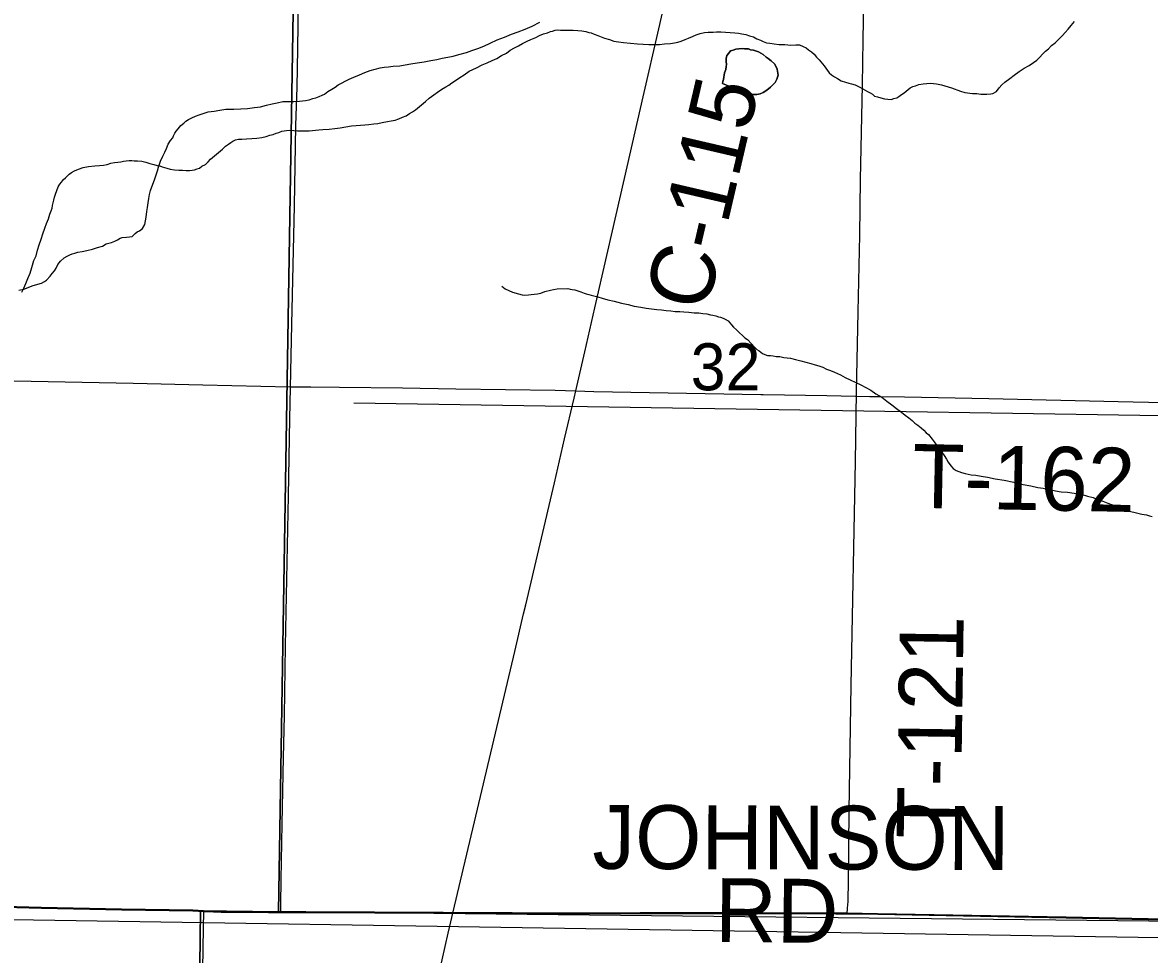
# Model space of a CAD drawing. Extents: x 2.4 to 73.1, y 4.5 to 25.6.
# Drawn here: x 43.39 to 43.892, y 18.583 to 18.998 of the extents above; entities that cross this region are included whole.
import ezdxf

# ---------------------------------------------------------------- set-up
doc = ezdxf.new("R2010")
doc.units = 0
for name, color, linetype in [('GM_X_County_Road', 7, 'Continuous'), ('GM_X_County_Road_Text', 7, 'Continuous'), ('GM_X_Interchange_Ramps', 7, 'Continuous'), ('GM_X_Minor_Lake', 7, 'Continuous'), ('GM_X_Minor_River', 7, 'Continuous'), ('GM_X_Section', 7, 'Continuous'), ('GM_X_Section_Text', 7, 'Continuous'), ('GM_X_Township', 7, 'Continuous'), ('GM_X_Township_Road', 7, 'Continuous'), ('GM_X_Township_Road_Text', 7, 'Continuous'), ('GM_X_US_Shield', 7, 'Continuous')]:
    doc.layers.add(name, color=color, linetype=linetype)

msp = doc.modelspace()

# ---------------------------------------------------------------- linework, layer by layer
at = {"layer": 'GM_X_County_Road'}
msp.add_line((43.60907, 18.71768), (43.61292, 18.73432), dxfattribs=at)
for points in [[(43.63623, 18.83366), (43.6402, 18.85095), (43.64472, 18.87063), (43.65791, 18.92819), (43.66613, 18.96457), (43.67319, 18.99479), (43.67664, 19.00993), (43.68375, 19.04178), (43.69135, 19.07512), (43.6983, 19.10383), (43.70422, 19.12638), (43.71071, 19.15039), (43.7175, 19.1743), (43.72344, 19.19524), (43.74391, 19.26696), (43.75788, 19.3163), (43.76276, 19.33357)], [(43.61292, 18.73432), (43.61388, 18.73842), (43.62668, 18.79269), (43.63123, 18.81232), (43.63547, 18.83041), (43.63623, 18.83366)], [(43.57593, 18.57695), (43.57673, 18.58043), (43.57937, 18.59218), (43.58222, 18.60427), (43.59509, 18.65871), (43.60907, 18.71768)]]:
    msp.add_lwpolyline(points, dxfattribs=at)
at = {"layer": 'GM_X_Interchange_Ramps'}
msp.add_lwpolyline([(43.9276, 18.59787), (43.85453, 18.5994), (43.77058, 18.6009), (43.757, 18.60107), (43.75192, 18.60113), (43.70838, 18.60123), (43.66485, 18.60125), (43.63841, 18.60118), (43.51594, 18.60166), (43.50475, 18.60171), (43.49917, 18.60173), (43.48509, 18.60186), (43.47809, 18.60192), (43.47479, 18.60206), (43.47037, 18.60218), (43.4656, 18.6024), (43.4339, 18.60285), (43.39809, 18.6036), (43.34828, 18.60502)], dxfattribs=at)
at = {"layer": 'GM_X_Minor_Lake'}
for points in [[(43.7197, 18.98329), (43.71857, 18.98389), (43.71763, 18.98448), (43.71669, 18.98488), (43.71537, 18.98529), (43.71405, 18.98551), (43.7131, 18.98591), (43.71139, 18.98595), (43.71025, 18.98597), (43.70873, 18.98582), (43.7074, 18.98566), (43.70625, 18.9853), (43.7051, 18.98495), (43.70432, 18.98402), (43.70353, 18.9829), (43.70312, 18.98158), (43.70309, 18.98025), (43.70325, 18.97892), (43.70323, 18.97797), (43.70301, 18.97664), (43.7024, 18.97514), (43.70196, 18.9723), (43.70175, 18.97135), (43.70154, 18.97041)], [(43.70154, 18.97041), (43.70175, 18.97135), (43.70196, 18.9723), (43.7024, 18.97514), (43.70301, 18.97664), (43.70323, 18.97797), (43.70325, 18.97892), (43.70309, 18.98025), (43.70312, 18.98158), (43.70353, 18.9829), (43.70432, 18.98402), (43.7051, 18.98495), (43.70625, 18.9853), (43.7074, 18.98566), (43.70873, 18.98582), (43.71025, 18.98597), (43.71139, 18.98595), (43.7131, 18.98591), (43.71405, 18.98551), (43.71537, 18.98529), (43.71669, 18.98488), (43.71763, 18.98448), (43.71857, 18.98389), (43.7197, 18.98329), (43.721, 18.98212), (43.72194, 18.98153), (43.72325, 18.98055), (43.72474, 18.97919), (43.72547, 18.97784), (43.72583, 18.97688), (43.72634, 18.97421), (43.72572, 18.97233), (43.72493, 18.97083), (43.72376, 18.96971), (43.72298, 18.96878), (43.72202, 18.96804), (43.72085, 18.96712), (43.7197, 18.96639), (43.71835, 18.96585), (43.71682, 18.9655), (43.71549, 18.96553), (43.71359, 18.96558), (43.71189, 18.9658), (43.71019, 18.96641), (43.70868, 18.96702), (43.70737, 18.96781), (43.70587, 18.9686), (43.70154, 18.97041)], [(43.70154, 18.97041), (43.70587, 18.9686), (43.70737, 18.96781), (43.70868, 18.96702), (43.71019, 18.96641), (43.71189, 18.9658), (43.71359, 18.96558), (43.71549, 18.96553), (43.71682, 18.9655), (43.71835, 18.96585), (43.7197, 18.96639), (43.72085, 18.96712), (43.72202, 18.96804), (43.72298, 18.96878), (43.72376, 18.96971), (43.72493, 18.97083), (43.72572, 18.97233), (43.72634, 18.97421), (43.72583, 18.97688), (43.72547, 18.97784), (43.72474, 18.97919), (43.72325, 18.98055), (43.72194, 18.98153), (43.721, 18.98212), (43.7197, 18.98329)]]:
    msp.add_lwpolyline(points, dxfattribs=at)
at = {"layer": 'GM_X_Minor_River'}
for points in [[(43.47253, 18.95781), (43.4752, 18.95813), (43.47768, 18.95864), (43.48035, 18.95896), (43.48396, 18.95907), (43.48701, 18.95919), (43.49005, 18.95931), (43.4931, 18.95981), (43.49577, 18.96013), (43.49845, 18.96083), (43.50093, 18.96134), (43.50323, 18.96186), (43.50571, 18.96237), (43.508, 18.96251), (43.51066, 18.96245), (43.51313, 18.96259), (43.5158, 18.96291), (43.51752, 18.96325), (43.51905, 18.96378), (43.52039, 18.96413), (43.52192, 18.96467), (43.52326, 18.96521), (43.52423, 18.96575), (43.52577, 18.96686), (43.52751, 18.96796), (43.52905, 18.96887), (43.5304, 18.96979), (43.53521, 18.97234), (43.53732, 18.97324), (43.53982, 18.97433), (43.54232, 18.97541), (43.54462, 18.97631), (43.54691, 18.97683), (43.54901, 18.97735), (43.55092, 18.97769), (43.55283, 18.97783), (43.55492, 18.97816), (43.55778, 18.97829), (43.56026, 18.9788), (43.56274, 18.97913), (43.5656, 18.97963), (43.56866, 18.98013), (43.57171, 18.98063), (43.57438, 18.98114), (43.57668, 18.98166), (43.57916, 18.98217), (43.58164, 18.98269), (43.58413, 18.98339), (43.58757, 18.98426), (43.58987, 18.98516), (43.59255, 18.98605), (43.59524, 18.98713), (43.59812, 18.98839), (43.60119, 18.98984), (43.60446, 18.9911), (43.60753, 18.99236), (43.61059, 18.99343), (43.61366, 18.99469), (43.61673, 18.99595), (43.62019, 18.99777)], [(43.76234, 18.96903), (43.76403, 18.96804), (43.76609, 18.96685), (43.76722, 18.96626), (43.76835, 18.96566), (43.76928, 18.96488), (43.7706, 18.96447), (43.77211, 18.96406), (43.77363, 18.96364), (43.77514, 18.96342), (43.77666, 18.96338), (43.77781, 18.96374), (43.77915, 18.96409), (43.78011, 18.96464), (43.78127, 18.96556), (43.78243, 18.96629), (43.78418, 18.96777), (43.78514, 18.96851), (43.7863, 18.96905), (43.78744, 18.96941), (43.78898, 18.96994), (43.79089, 18.97028), (43.79412, 18.97059), (43.79678, 18.97034), (43.79905, 18.9699), (43.80358, 18.96847), (43.80754, 18.96705), (43.80943, 18.96644), (43.81284, 18.96598), (43.81474, 18.96594), (43.81664, 18.96571), (43.8193, 18.96564), (43.82101, 18.9658), (43.82197, 18.96596), (43.82351, 18.96688), (43.82469, 18.96856), (43.82586, 18.96986), (43.82721, 18.97097), (43.82953, 18.97263), (43.83147, 18.97411), (43.83359, 18.97577), (43.83591, 18.97723), (43.83803, 18.97851), (43.83996, 18.9798), (43.8415, 18.98091), (43.84287, 18.9822), (43.84403, 18.98351), (43.8454, 18.98481), (43.84675, 18.98591), (43.84812, 18.9874), (43.84966, 18.98851), (43.85083, 18.98981), (43.852, 18.99092), (43.85297, 18.99185), (43.85414, 18.99315), (43.8555, 18.99464), (43.85687, 18.99632), (43.85824, 18.998)], [(43.58101, 18.97068), (43.58256, 18.97178), (43.58449, 18.97306), (43.58642, 18.97435), (43.58874, 18.97601), (43.592, 18.97745), (43.5945, 18.97872), (43.5968, 18.97962), (43.59892, 18.98071), (43.60103, 18.98162), (43.60315, 18.9829), (43.60527, 18.98399), (43.60701, 18.98528), (43.60893, 18.98637), (43.61066, 18.98728), (43.6124, 18.9882), (43.61451, 18.98929), (43.61624, 18.99001), (43.61835, 18.99091), (43.62008, 18.99182), (43.62181, 18.99254), (43.62353, 18.99307), (43.62488, 18.99361), (43.62583, 18.99378), (43.62698, 18.99413), (43.62812, 18.9943), (43.62945, 18.99426), (43.63097, 18.99423), (43.63306, 18.99418), (43.63496, 18.99414), (43.63705, 18.99409), (43.63895, 18.99386), (43.64066, 18.99363), (43.64198, 18.99322), (43.64311, 18.993), (43.64443, 18.99241), (43.64594, 18.9918), (43.64744, 18.9912), (43.64895, 18.99059), (43.65122, 18.98997), (43.65311, 18.98936), (43.65519, 18.98893), (43.65746, 18.98869), (43.66373, 18.98817), (43.66619, 18.98792), (43.66866, 18.98787), (43.67094, 18.98782), (43.67341, 18.98776), (43.6757, 18.98809), (43.67837, 18.98822), (43.68008, 18.98856), (43.68161, 18.9889), (43.68314, 18.98925), (43.68487, 18.98997), (43.68641, 18.99069), (43.68813, 18.99141), (43.68986, 18.99213), (43.69158, 18.99266), (43.6935, 18.99319), (43.69521, 18.99334), (43.6973, 18.99329), (43.69883, 18.99345), (43.70073, 18.99341), (43.70282, 18.99336), (43.7049, 18.99312), (43.70699, 18.99307), (43.7087, 18.99285), (43.71021, 18.99262), (43.71192, 18.9922), (43.71361, 18.9916), (43.71531, 18.99118), (43.71682, 18.99038), (43.71851, 18.98977), (43.71964, 18.98918), (43.72115, 18.98858), (43.72266, 18.98835), (43.72456, 18.98812), (43.72684, 18.98788), (43.72931, 18.98782), (43.73196, 18.98757), (43.73425, 18.98771), (43.73577, 18.98767), (43.73746, 18.98687), (43.73878, 18.98628), (43.7399, 18.98549), (43.74121, 18.98451), (43.74233, 18.98354), (43.74344, 18.98218), (43.74455, 18.98102), (43.74603, 18.97927), (43.74677, 18.97831), (43.74898, 18.97522), (43.7501, 18.97424), (43.75141, 18.97345), (43.75273, 18.97266), (43.75442, 18.97168), (43.7563, 18.97106), (43.75782, 18.97065), (43.75895, 18.97024), (43.76065, 18.96983), (43.76234, 18.96903)], [(43.40896, 18.92843), (43.41051, 18.9301), (43.41167, 18.93083), (43.41302, 18.93156), (43.41475, 18.93228), (43.41685, 18.933), (43.41915, 18.93351), (43.42201, 18.93383), (43.4241, 18.93397), (43.42581, 18.93412), (43.42753, 18.93446), (43.42907, 18.935), (43.43078, 18.93534), (43.43231, 18.93549), (43.43364, 18.93565), (43.43479, 18.93582), (43.43593, 18.93598), (43.43727, 18.93614), (43.43841, 18.93611), (43.43955, 18.93609), (43.44107, 18.93605), (43.44296, 18.93582), (43.44466, 18.9354), (43.44655, 18.93479), (43.44825, 18.93437), (43.44976, 18.93396), (43.4509, 18.93374), (43.45203, 18.93334), (43.45411, 18.93272), (43.45562, 18.93231), (43.45752, 18.93207), (43.45941, 18.93184), (43.46112, 18.9318), (43.46264, 18.93177), (43.46416, 18.93173), (43.46531, 18.9319), (43.46645, 18.93206), (43.4676, 18.93241), (43.46856, 18.93277), (43.46972, 18.9337), (43.47126, 18.93442), (43.47242, 18.93553), (43.47359, 18.93684), (43.47883, 18.94128), (43.48019, 18.94257), (43.48154, 18.94349), (43.48251, 18.94423), (43.48347, 18.94478), (43.48462, 18.94532), (43.48596, 18.94567), (43.48748, 18.94564), (43.48958, 18.94578), (43.49186, 18.94592), (43.49414, 18.94606), (43.49643, 18.94639), (43.49835, 18.94691), (43.49988, 18.94745), (43.50141, 18.94779), (43.50275, 18.94833), (43.5039, 18.94868), (43.50524, 18.94922), (43.50734, 18.94956), (43.50887, 18.94971), (43.51057, 18.94948), (43.51228, 18.94944), (43.51399, 18.9494), (43.5157, 18.94937), (43.51741, 18.94933), (43.51894, 18.94948), (43.52027, 18.94964), (43.5218, 18.9498), (43.52351, 18.94995), (43.52636, 18.95007), (43.52884, 18.9504), (43.53132, 18.95072), (43.5338, 18.95123), (43.53628, 18.95156), (43.53838, 18.9517), (43.54028, 18.95185), (43.54219, 18.95199), (43.54409, 18.95214), (43.54619, 18.95247), (43.54809, 18.95262), (43.55001, 18.95315), (43.5523, 18.95347), (43.55401, 18.95382), (43.55573, 18.95416), (43.55746, 18.95469), (43.55899, 18.95541), (43.56072, 18.95613), (43.56207, 18.95705), (43.56342, 18.95778), (43.56477, 18.9587), (43.56923, 18.9624), (43.57097, 18.96388), (43.57291, 18.96535), (43.57465, 18.96664), (43.57658, 18.96793), (43.57831, 18.96903), (43.57966, 18.96976), (43.58101, 18.97068)], [(43.38823, 18.87843), (43.39033, 18.87895), (43.39225, 18.87967), (43.39416, 18.88038), (43.39665, 18.88109), (43.39818, 18.88162), (43.39953, 18.88235), (43.40049, 18.8829), (43.40206, 18.88476), (43.40303, 18.88588), (43.40401, 18.887), (43.4048, 18.88831), (43.40559, 18.88981), (43.40677, 18.8913), (43.40832, 18.89279), (43.40967, 18.89352), (43.41083, 18.89425), (43.41197, 18.8946), (43.41312, 18.89496), (43.41446, 18.89531), (43.41637, 18.89564), (43.41847, 18.89617), (43.42096, 18.89668), (43.42325, 18.89739), (43.42536, 18.8981), (43.42709, 18.89901), (43.42939, 18.89972), (43.43092, 18.90025), (43.43208, 18.9008), (43.43323, 18.90153), (43.43419, 18.90189), (43.4361, 18.90203), (43.43743, 18.90219), (43.43857, 18.90236), (43.43993, 18.90366), (43.4409, 18.9044), (43.44186, 18.90494), (43.44322, 18.90586), (43.44421, 18.90774), (43.44462, 18.90925), (43.44485, 18.91095), (43.4451, 18.91342), (43.44552, 18.91531), (43.44576, 18.91739), (43.44599, 18.91928), (43.44641, 18.92098), (43.44683, 18.92287), (43.44866, 18.92796), (43.44927, 18.92985), (43.44988, 18.93154), (43.4503, 18.93324), (43.45131, 18.93588), (43.45231, 18.93813), (43.45311, 18.93982), (43.45391, 18.94152), (43.45471, 18.9434), (43.4557, 18.94508), (43.45668, 18.9462), (43.45708, 18.94714), (43.45767, 18.94827), (43.45827, 18.9492), (43.45905, 18.95033), (43.46023, 18.95182), (43.46158, 18.95274), (43.46255, 18.95366), (43.46371, 18.9544), (43.46524, 18.95512), (43.46678, 18.95585), (43.46851, 18.95657), (43.47023, 18.9571), (43.47253, 18.95781)], [(43.38956, 18.87759), (43.39035, 18.87928), (43.39135, 18.88135), (43.39216, 18.88361), (43.39317, 18.88605), (43.39399, 18.8885), (43.39482, 18.89171), (43.39582, 18.89378), (43.39644, 18.89623), (43.39726, 18.89868), (43.39807, 18.90113), (43.39889, 18.90359), (43.39971, 18.90603), (43.40051, 18.90811), (43.40132, 18.91018), (43.40194, 18.91225), (43.40254, 18.91376), (43.40295, 18.91489), (43.40317, 18.91621), (43.40338, 18.91735), (43.40379, 18.91848), (43.40401, 18.9198), (43.40442, 18.92112), (43.40564, 18.92451), (43.40642, 18.92563), (43.4072, 18.92657), (43.40799, 18.92769), (43.40896, 18.92843)], [(43.60327, 18.88021), (43.60477, 18.87903), (43.60797, 18.87763), (43.61061, 18.87681), (43.61231, 18.8764), (43.61345, 18.87618), (43.61516, 18.87633), (43.61631, 18.87649), (43.61764, 18.87665), (43.61916, 18.87681), (43.62069, 18.87716), (43.62242, 18.87788), (43.6249, 18.87839), (43.62624, 18.87874), (43.62796, 18.87908), (43.63272, 18.87916), (43.63366, 18.87895), (43.63461, 18.87874), (43.63574, 18.87853), (43.63706, 18.87812), (43.63839, 18.87771), (43.63989, 18.8771), (43.64084, 18.87689), (43.64197, 18.87649), (43.64311, 18.87627), (43.64424, 18.87586), (43.64594, 18.87545), (43.64801, 18.87483), (43.65047, 18.8742), (43.65331, 18.87357), (43.65652, 18.87274), (43.65955, 18.8721), (43.66219, 18.87128), (43.66522, 18.87083), (43.6675, 18.8704), (43.66996, 18.87015), (43.67224, 18.86991), (43.67432, 18.86968), (43.67641, 18.86944), (43.67849, 18.8692), (43.68039, 18.86897), (43.68248, 18.86892), (43.68438, 18.86888), (43.68647, 18.86864), (43.68893, 18.8684), (43.69102, 18.86835), (43.69273, 18.86812), (43.69462, 18.86789), (43.69613, 18.86747), (43.69727, 18.86726), (43.6986, 18.86704), (43.69973, 18.86663), (43.70067, 18.86642), (43.7018, 18.86602), (43.70275, 18.86562), (43.70406, 18.86483), (43.70554, 18.86308), (43.70646, 18.86192), (43.70777, 18.86075), (43.70907, 18.8594), (43.71037, 18.85823), (43.71149, 18.85725), (43.71261, 18.85647), (43.71596, 18.85297), (43.71689, 18.852), (43.71782, 18.85141), (43.71932, 18.85024), (43.72045, 18.84983), (43.72158, 18.84943), (43.72291, 18.8494), (43.72405, 18.84918), (43.72537, 18.84896), (43.72708, 18.84892), (43.72878, 18.8485), (43.73182, 18.84825), (43.73409, 18.84762), (43.73635, 18.847), (43.73862, 18.84638), (43.74089, 18.84576), (43.74277, 18.84515), (43.74448, 18.84473), (43.74617, 18.84412), (43.74787, 18.84332), (43.74956, 18.84272), (43.75145, 18.84191), (43.75408, 18.84072), (43.75614, 18.83953), (43.7584, 18.83853), (43.76085, 18.83733), (43.76311, 18.83633), (43.76536, 18.83514), (43.76761, 18.83395), (43.76986, 18.83238), (43.77249, 18.8308), (43.77473, 18.82904), (43.77697, 18.82747), (43.77902, 18.82572), (43.78127, 18.82415), (43.78295, 18.82278), (43.78444, 18.82161), (43.78594, 18.82043)], [(43.5373, 18.82828), (44.59696, 18.81169)], [(43.78594, 18.82043), (43.78724, 18.81926), (43.78855, 18.81829), (43.79005, 18.81711), (43.79116, 18.81614), (43.79228, 18.81497), (43.79321, 18.81419), (43.79487, 18.81206), (43.7958, 18.8109), (43.79654, 18.80994), (43.79727, 18.80878), (43.79949, 18.80588), (43.80023, 18.80492), (43.80133, 18.80318), (43.80206, 18.80184), (43.80316, 18.80029), (43.80428, 18.79913), (43.80559, 18.79815), (43.80672, 18.79774), (43.80804, 18.79733), (43.80955, 18.79692), (43.8122, 18.79629), (43.81428, 18.79605), (43.81674, 18.79562), (43.81959, 18.79517), (43.82299, 18.79453), (43.82697, 18.79387), (43.83132, 18.79301), (43.83548, 18.79197), (43.83889, 18.79132), (43.84192, 18.79068), (43.84438, 18.79025), (43.84608, 18.78983), (43.84797, 18.7896), (43.84987, 18.78917), (43.85233, 18.78874), (43.85517, 18.78848), (43.8582, 18.78803), (43.86123, 18.78759), (43.86407, 18.78676), (43.86653, 18.78614), (43.8686, 18.78533), (43.87086, 18.78452), (43.87312, 18.78371), (43.87633, 18.7825), (43.87896, 18.7813), (43.88198, 18.78028), (43.88538, 18.77944), (43.88822, 18.77881), (43.8903, 18.77838), (43.89162, 18.77797), (43.89295, 18.77776)], [(42.98775, 18.60453), (44.0474, 18.58794)]]:
    msp.add_lwpolyline(points, dxfattribs=at)
at = {"layer": 'GM_X_Section'}
for points in [[(42.98358, 19.11451), (43.51203, 19.10261), (43.50379, 18.60175), (43.46912, 18.60216), (42.96961, 18.61131)], [(43.51203, 19.10261), (44.01453, 19.09983), (44.00623, 18.5965), (43.97458, 18.59666), (43.50379, 18.60175)]]:
    msp.add_lwpolyline(points, close=True, dxfattribs=at)
at = {"layer": 'GM_X_Township'}
msp.add_lwpolyline([(43.9276, 18.59787), (43.85453, 18.5994), (43.77058, 18.6009), (43.757, 18.60107), (43.75192, 18.60113), (43.70838, 18.60123), (43.66485, 18.60125), (43.63841, 18.60118), (43.51594, 18.60166), (43.50475, 18.60171), (43.49917, 18.60173), (43.48509, 18.60186), (43.47809, 18.60192), (43.47479, 18.60206), (43.47037, 18.60218), (43.4656, 18.6024), (43.4339, 18.60285), (43.39809, 18.6036), (43.34828, 18.60502)], dxfattribs=at)
at = {"layer": 'GM_X_Township_Road'}
for points in [[(43.51217, 18.96877), (43.51245, 18.98587), (43.51277, 19.00763), (43.51344, 19.05271), (43.51429, 19.09623), (43.51441, 19.10259)], [(43.75712, 18.60079), (43.75727, 18.6033), (43.75744, 18.6064), (43.75766, 18.61571), (43.758, 18.64676), (43.7589, 18.70266), (43.76071, 18.80202), (43.76123, 18.83307), (43.76196, 18.86877), (43.76269, 18.90293), (43.76303, 18.92777), (43.76385, 18.96969), (43.76419, 18.98987), (43.76481, 19.02402), (43.76576, 19.0706), (43.7663, 19.09078), (43.76637, 19.09924), (43.76638, 19.10109)], [(43.50487, 18.60144), (43.50491, 18.60509), (43.50503, 18.61597), (43.50548, 18.64084), (43.50601, 18.67037), (43.50649, 18.68902), (43.5069, 18.72011), (43.50823, 18.78694), (43.50888, 18.82113), (43.5097, 18.8631), (43.51096, 18.91594), (43.51157, 18.95168), (43.51217, 18.96877)], [(43.26839, 18.84066), (43.2734, 18.84055), (43.30591, 18.83983), (43.36324, 18.83849), (43.43912, 18.8371), (43.47016, 18.83635), (43.50881, 18.83545), (43.51821, 18.83544)], [(43.51821, 18.83544), (43.53091, 18.83534), (43.55904, 18.83493), (43.5828, 18.83459), (43.62707, 18.83395), (43.63623, 18.83366)], [(43.63623, 18.83366), (43.64424, 18.8334), (43.69377, 18.83244), (43.71858, 18.83207), (43.71957, 18.83205)], [(43.71957, 18.83205), (43.74794, 18.83161), (43.76715, 18.83116)], [(43.76715, 18.83116), (43.77183, 18.83112), (43.78251, 18.83094), (43.82011, 18.8303), (43.87771, 18.82894), (43.89796, 18.82849), (43.94777, 18.82707), (43.98358, 18.82632), (44.01527, 18.82587), (44.02004, 18.82565)], [(43.21759, 18.60742), (43.22228, 18.60737), (43.23296, 18.60719), (43.27055, 18.60656), (43.32815, 18.60519), (43.3484, 18.60475), (43.39821, 18.60332), (43.43402, 18.60258), (43.46572, 18.60212), (43.47048, 18.60191)], [(43.46565, 18.35346), (43.46611, 18.35401), (43.4666, 18.35468), (43.46693, 18.35535), (43.46723, 18.35648), (43.46748, 18.35762), (43.46756, 18.36075), (43.46784, 18.3762), (43.46801, 18.40565), (43.46835, 18.42579), (43.46883, 18.46453), (43.46936, 18.50791), (43.46955, 18.5265), (43.47015, 18.57608), (43.47039, 18.59467), (43.47048, 18.60191)], [(43.47048, 18.60191), (43.47491, 18.60178), (43.47821, 18.60165), (43.48521, 18.60158), (43.49929, 18.60145), (43.50487, 18.60144)], [(43.50487, 18.60144), (43.51606, 18.60138), (43.63853, 18.60091), (43.66496, 18.60097), (43.7085, 18.60096), (43.75204, 18.60085), (43.75712, 18.60079)], [(43.75712, 18.60079), (43.7707, 18.60063), (43.85465, 18.59913), (43.92772, 18.5976), (43.97047, 18.59655), (43.9738, 18.5964), (43.97543, 18.59609), (43.97713, 18.59555), (43.97795, 18.59529)]]:
    msp.add_lwpolyline(points, dxfattribs=at)
at = {"layer": 'GM_X_US_Shield'}
for points in [[(42.95709, 18.10511), (43.46297, 18.10511), (43.46912, 18.60216), (42.96961, 18.61131)], [(43.46297, 18.10511), (43.96998, 18.10511), (43.97458, 18.59666), (43.50379, 18.60175), (43.46912, 18.60216)]]:
    msp.add_lwpolyline(points, close=True, dxfattribs=at)

# ---------------------------------------------------------------- texts
at = {"layer": 'GM_X_County_Road_Text'}
msp.add_text('C-115', height=0.028409, rotation=76.9017, dxfattribs=at).set_placement((43.69458, 18.86814))
at = {"layer": 'GM_X_Section_Text'}
msp.add_text('32', height=0.020928, rotation=0, dxfattribs=at).set_placement((43.68735, 18.83387))
at = {"layer": 'GM_X_Township_Road_Text'}
for s, rotation, p in [('T-162', 358.8872, (43.78583, 18.78162)), ('T-121', 89.1545, (43.80749, 18.63415)), ('JOHNSON', 359.8489, (43.64357, 18.62085)), ('RD', 359.5022, (43.69812, 18.58834))]:
    msp.add_text(s, height=0.028409, rotation=rotation, dxfattribs=at).set_placement(p)

doc.saveas('drawing.dxf')
